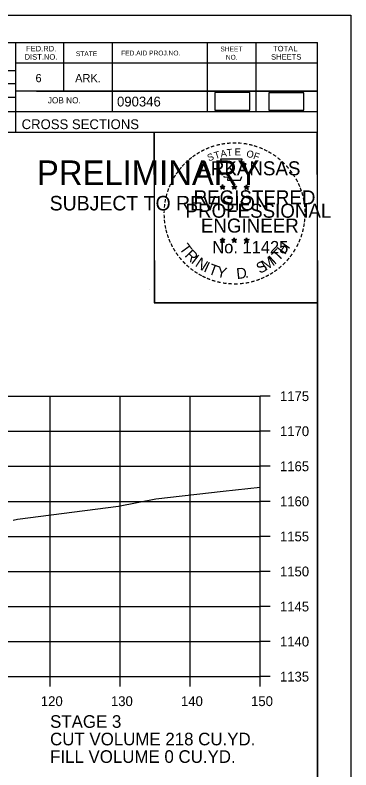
# Model space of a CAD drawing. Extents: x 1368971 to 1374497, y 378717 to 381839.
# Drawn here: x 1371167.7 to 1371215.6, y 379036.1 to 379143.8 of the extents above; entities that cross this region are included whole.
import ezdxf

# ---------------------------------------------------------------- set-up
doc = ezdxf.new("R2010")
doc.units = 0
for name, color, linetype in [('R_Axis', 7, 'Continuous'), ('R_Axis Annot', 7, 'Continuous'), ('R_Border', 7, 'Continuous'), ('R_Border PE', 7, 'Continuous'), ('R_Border Prem', 7, 'Continuous'), ('R_Exist Surface', 7, 'Continuous'), ('R_Grid', 7, 'Continuous'), ('R_No Plot', 7, 'Continuous'), ('R_Water', 7, 'Continuous')]:
    doc.layers.add(name, color=color, linetype=linetype)

msp = doc.modelspace()

# ---------------------------------------------------------------- linework, layer by layer
at = {"layer": 'R_Axis'}
for p, q in [((1371202.71, 379049.4), (1371202.71, 379089.4)), ((1371204.11, 379089.4), (1371202.71, 379089.4)), ((1371204.11, 379084.4), (1371202.71, 379084.4)), ((1371204.11, 379079.4), (1371202.71, 379079.4)), ((1371204.11, 379074.4), (1371202.71, 379074.4)), ((1371204.11, 379069.4), (1371202.71, 379069.4)), ((1371204.11, 379064.4), (1371202.71, 379064.4)), ((1371204.11, 379059.4), (1371202.71, 379059.4)), ((1371204.11, 379054.4), (1371202.71, 379054.4)), ((1370902.71, 379049.4), (1371202.71, 379049.4)), ((1371172.71, 379048), (1371172.71, 379049.4)), ((1371182.71, 379048), (1371182.71, 379049.4)), ((1371192.71, 379048), (1371192.71, 379049.4)), ((1371202.71, 379048), (1371202.71, 379049.4)), ((1371204.11, 379049.4), (1371202.71, 379049.4))]:
    msp.add_line(p, q, dxfattribs=at)
at = {"layer": 'R_Border'}
for p, q in [((1370894.71, 379139.86), (1371210.89, 379139.86)), ((1371167.79, 379139.86), (1371167.79, 379127.06)), ((1371174.63, 379139.86), (1371174.63, 379132.92)), ((1371181.57, 379139.86), (1371181.57, 379129.98)), ((1371195.15, 379139.86), (1371195.15, 379129.98)), ((1371202.09, 379139.86), (1371202.09, 379129.98)), ((1371210.89, 378934.4), (1371210.89, 379139.86)), ((1371210.89, 379136.92), (1371167.79, 379136.92)), ((1371210.89, 379136.94), (1371210.89, 379136.94)), ((1371128.63, 379135.84), (1371167.79, 379135.84)), ((1371128.63, 379133.98), (1371167.79, 379133.98)), ((1371210.89, 379132.92), (1371167.79, 379132.92)), ((1371170.75, 379132.92), (1371210.89, 379132.92)), ((1371128.63, 379132.04), (1371167.79, 379132.04)), ((1371210.89, 379129.98), (1371128.63, 379129.98)), ((1371167.79, 379127.06), (1371210.89, 379127.06))]:
    msp.add_line(p, q, dxfattribs=at)
at = {"layer": 'R_Border PE'}
for p, q in [((1371197.32, 379119.57), (1371197.28, 379119.32)), ((1371197.32, 379119.2), (1371197.32, 379119.57)), ((1371197.32, 379119.57), (1371197.37, 379119.32)), ((1371198.99, 379119.57), (1371198.95, 379119.32)), ((1371198.99, 379119.2), (1371198.99, 379119.57)), ((1371198.99, 379119.57), (1371199.04, 379119.32)), ((1371200.76, 379119.56), (1371200.72, 379119.3)), ((1371200.76, 379119.19), (1371200.76, 379119.56)), ((1371200.76, 379119.56), (1371200.81, 379119.31)), ((1371196.97, 379119.31), (1371197.32, 379119.2)), ((1371196.97, 379119.31), (1371197.23, 379119.27)), ((1371196.97, 379119.31), (1371197.21, 379119.19)), ((1371197.11, 379118.91), (1371197.32, 379119.2)), ((1371197.11, 379118.91), (1371197.23, 379119.15)), ((1371197.11, 379118.91), (1371197.32, 379119.12)), ((1371197.67, 379119.31), (1371197.32, 379119.2)), ((1371197.54, 379118.91), (1371197.32, 379119.2)), ((1371197.54, 379118.91), (1371197.32, 379119.12)), ((1371197.67, 379119.31), (1371197.38, 379119.27)), ((1371197.54, 379118.91), (1371197.4, 379119.2)), ((1371197.67, 379119.31), (1371197.47, 379119.21)), ((1371198.64, 379119.31), (1371198.99, 379119.2)), ((1371198.64, 379119.31), (1371198.9, 379119.27)), ((1371198.64, 379119.31), (1371198.88, 379119.19)), ((1371198.78, 379118.91), (1371198.99, 379119.2)), ((1371198.78, 379118.91), (1371198.9, 379119.15)), ((1371198.78, 379118.91), (1371198.99, 379119.12)), ((1371199.34, 379119.31), (1371198.99, 379119.2)), ((1371199.21, 379118.91), (1371198.99, 379119.2)), ((1371199.21, 379118.91), (1371198.99, 379119.12)), ((1371199.34, 379119.31), (1371199.05, 379119.27)), ((1371199.21, 379118.91), (1371199.07, 379119.2)), ((1371199.34, 379119.31), (1371199.14, 379119.21)), ((1371200.41, 379119.3), (1371200.76, 379119.19)), ((1371200.41, 379119.3), (1371200.66, 379119.26)), ((1371200.41, 379119.3), (1371200.64, 379119.18)), ((1371200.54, 379118.89), (1371200.76, 379119.19)), ((1371200.54, 379118.89), (1371200.67, 379119.14)), ((1371200.54, 379118.89), (1371200.75, 379119.11)), ((1371200.97, 379118.89), (1371200.75, 379119.11)), ((1371201.1, 379119.3), (1371200.76, 379119.19)), ((1371200.97, 379118.89), (1371200.76, 379119.19)), ((1371201.1, 379119.3), (1371200.82, 379119.25)), ((1371200.97, 379118.89), (1371200.83, 379119.19)), ((1371201.1, 379119.3), (1371200.9, 379119.2)), ((1371197.32, 379112), (1371197.28, 379111.74)), ((1371197.32, 379111.63), (1371197.32, 379112)), ((1371197.32, 379112), (1371197.37, 379111.75)), ((1371198.99, 379112), (1371198.95, 379111.74)), ((1371198.99, 379111.63), (1371198.99, 379112)), ((1371198.99, 379112), (1371199.04, 379111.75)), ((1371200.75, 379111.99), (1371200.71, 379111.73)), ((1371200.75, 379111.62), (1371200.75, 379111.99)), ((1371200.75, 379111.99), (1371200.8, 379111.74)), ((1371196.97, 379111.74), (1371197.32, 379111.63)), ((1371196.97, 379111.74), (1371197.22, 379111.7)), ((1371196.97, 379111.74), (1371197.21, 379111.62)), ((1371197.1, 379111.33), (1371197.32, 379111.63)), ((1371197.1, 379111.33), (1371197.23, 379111.58)), ((1371197.1, 379111.33), (1371197.32, 379111.55)), ((1371197.67, 379111.74), (1371197.32, 379111.63)), ((1371197.53, 379111.33), (1371197.32, 379111.63)), ((1371197.53, 379111.33), (1371197.32, 379111.55)), ((1371197.67, 379111.74), (1371197.38, 379111.69)), ((1371197.53, 379111.33), (1371197.39, 379111.62)), ((1371197.67, 379111.74), (1371197.46, 379111.64)), ((1371198.64, 379111.74), (1371198.99, 379111.63)), ((1371198.64, 379111.74), (1371198.89, 379111.7)), ((1371198.64, 379111.74), (1371198.88, 379111.62)), ((1371198.77, 379111.33), (1371198.99, 379111.63)), ((1371198.77, 379111.33), (1371198.9, 379111.58)), ((1371198.77, 379111.33), (1371198.99, 379111.55)), ((1371199.33, 379111.74), (1371198.99, 379111.63)), ((1371199.2, 379111.33), (1371198.99, 379111.63)), ((1371199.2, 379111.33), (1371198.99, 379111.55)), ((1371199.33, 379111.74), (1371199.05, 379111.69)), ((1371199.2, 379111.33), (1371199.06, 379111.62)), ((1371199.33, 379111.74), (1371199.13, 379111.64)), ((1371200.41, 379111.73), (1371200.75, 379111.62)), ((1371200.41, 379111.73), (1371200.66, 379111.69)), ((1371200.41, 379111.73), (1371200.64, 379111.61)), ((1371200.54, 379111.32), (1371200.75, 379111.62)), ((1371200.54, 379111.32), (1371200.66, 379111.57)), ((1371200.54, 379111.32), (1371200.75, 379111.54)), ((1371201.1, 379111.73), (1371200.75, 379111.62)), ((1371200.97, 379111.32), (1371200.75, 379111.62)), ((1371200.97, 379111.32), (1371200.75, 379111.54)), ((1371201.1, 379111.73), (1371200.82, 379111.68)), ((1371200.97, 379111.32), (1371200.83, 379111.61)), ((1371201.1, 379111.73), (1371200.9, 379111.63))]:
    msp.add_line(p, q, dxfattribs=at)
for points in [[(1371197.01, 379123.19), (1371197.28, 379122.37)], [(1371200.53, 379122.27), (1371200.67, 379122.55), (1371199.98, 379122.53), (1371200.13, 379123.19), (1371197.01, 379123.19)], [(1371197.51, 379120.77), (1371197.51, 379120.68), (1371198.07, 379120.66), (1371198.02, 379120.19), (1371199.89, 379120.19), (1371200.09, 379120.73)], [(1371197.32, 379119.57), (1371197.54, 379118.91), (1371196.97, 379119.31), (1371197.67, 379119.31), (1371197.11, 379118.91), (1371197.32, 379119.57)], [(1371198.99, 379119.57), (1371199.21, 379118.91), (1371198.64, 379119.31), (1371199.34, 379119.31), (1371198.78, 379118.91), (1371198.99, 379119.57)], [(1371200.76, 379119.56), (1371200.97, 379118.89), (1371200.41, 379119.3), (1371201.1, 379119.3), (1371200.54, 379118.89), (1371200.76, 379119.56)], [(1371197.32, 379112), (1371197.53, 379111.33), (1371196.97, 379111.74), (1371197.67, 379111.74), (1371197.1, 379111.33), (1371197.32, 379112)], [(1371198.99, 379112), (1371199.2, 379111.33), (1371198.64, 379111.74), (1371199.33, 379111.74), (1371198.77, 379111.33), (1371198.99, 379112)], [(1371200.75, 379111.99), (1371200.97, 379111.32), (1371200.41, 379111.73), (1371201.1, 379111.73), (1371200.54, 379111.32), (1371200.75, 379111.99)]]:
    msp.add_lwpolyline(points, dxfattribs=at)
for centre, radius in [((1371197.32, 379119.2), 0.172), ((1371197.32, 379119.2), 0.145), ((1371197.32, 379119.2), 0.116), ((1371197.32, 379119.2), 0.0991), ((1371197.32, 379119.2), 0.0747), ((1371197.32, 379119.2), 0.0495), ((1371197.32, 379119.2), 0.0296), ((1371198.99, 379119.2), 0.172), ((1371198.99, 379119.2), 0.145), ((1371198.99, 379119.2), 0.116), ((1371198.99, 379119.2), 0.0991), ((1371198.99, 379119.2), 0.0747), ((1371198.99, 379119.2), 0.0495), ((1371198.99, 379119.2), 0.0296), ((1371200.76, 379119.19), 0.172), ((1371200.76, 379119.19), 0.145), ((1371200.76, 379119.19), 0.116), ((1371200.76, 379119.19), 0.0991), ((1371200.76, 379119.19), 0.0747), ((1371200.76, 379119.19), 0.0495), ((1371200.76, 379119.19), 0.0296), ((1371197.32, 379111.63), 0.172), ((1371197.32, 379111.63), 0.145), ((1371197.32, 379111.63), 0.116), ((1371197.32, 379111.63), 0.0991), ((1371197.32, 379111.63), 0.0747), ((1371197.32, 379111.63), 0.0495), ((1371197.32, 379111.63), 0.0296), ((1371198.99, 379111.63), 0.172), ((1371198.99, 379111.63), 0.145), ((1371198.99, 379111.63), 0.116), ((1371198.99, 379111.63), 0.0991), ((1371198.99, 379111.63), 0.0747), ((1371198.99, 379111.63), 0.0495), ((1371198.99, 379111.63), 0.0296), ((1371200.75, 379111.62), 0.172), ((1371200.75, 379111.62), 0.145), ((1371200.75, 379111.62), 0.116), ((1371200.75, 379111.62), 0.0991), ((1371200.75, 379111.62), 0.0747), ((1371200.75, 379111.62), 0.0495), ((1371200.75, 379111.62), 0.0296)]:
    msp.add_circle(centre, radius, dxfattribs=at)
at = {"layer": 'R_Exist Surface'}
msp.add_lwpolyline([(1371167.45, 379071.74), (1371168.08, 379071.84), (1371182.48, 379073.69), (1371187.78, 379074.74), (1371197.4, 379075.86), (1371202.71, 379076.43)], dxfattribs=at)
at = {"layer": 'R_Grid'}
for p, q in [((1370902.71, 379089.4), (1371202.71, 379089.4)), ((1371172.71, 379049.4), (1371172.71, 379089.4)), ((1371182.71, 379049.4), (1371182.71, 379089.4)), ((1371192.71, 379049.4), (1371192.71, 379089.4)), ((1371202.71, 379049.4), (1371202.71, 379089.4)), ((1370902.71, 379084.4), (1371202.71, 379084.4)), ((1370902.71, 379079.4), (1371202.71, 379079.4)), ((1370902.71, 379074.4), (1371202.71, 379074.4)), ((1370902.71, 379069.4), (1371202.71, 379069.4)), ((1370902.71, 379064.4), (1371202.71, 379064.4)), ((1370902.71, 379059.4), (1371202.71, 379059.4)), ((1370902.71, 379054.4), (1371202.71, 379054.4)), ((1370902.71, 379049.4), (1371202.71, 379049.4))]:
    msp.add_line(p, q, dxfattribs=at)
at = {"layer": 'R_No Plot'}
for p, q in [((1370882.31, 379143.75), (1371215.64, 379143.75)), ((1371186.92, 379104.6), (1371186.92, 379104.6))]:
    msp.add_line(p, q, dxfattribs=at)
for points in [[(1370882.3, 379143.75), (1371215.64, 379143.75), (1371215.64, 378930.42), (1370882.3, 378930.42)], [(1371128.63, 379139.86), (1371128.63, 379129.98), (1371164.36, 379129.98), (1371164.36, 379127.06), (1371187.56, 379127.06), (1371187.56, 379102.73), (1371210.89, 379102.73), (1371210.89, 378934.4), (1370894.71, 378934.4), (1370894.71, 379139.86)], [(1371187.56, 379127.06), (1371210.77, 379127.06), (1371210.89, 379102.73), (1371187.68, 379102.73)]]:
    msp.add_lwpolyline(points, close=True, dxfattribs=at)
at = {"layer": 'R_Water'}
for points in [[(1371196.21, 379130.21), (1371201.21, 379130.21), (1371201.21, 379132.71), (1371196.21, 379132.71)], [(1371203.94, 379130.18), (1371208.94, 379130.18), (1371208.94, 379132.68), (1371203.94, 379132.68)]]:
    msp.add_lwpolyline(points, close=True, dxfattribs=at)

# ---------------------------------------------------------------- texts
at = {"layer": 'R_Axis Annot'}
for s, height, p in [('1175', 1.4, (1371205.51, 379088.7)), ('1170', 1.4, (1371205.51, 379083.7)), ('1165', 1.4, (1371205.51, 379078.7)), ('1160', 1.4, (1371205.51, 379073.7)), ('1155', 1.4, (1371205.51, 379068.7)), ('1150', 1.4, (1371205.51, 379063.7)), ('1145', 1.4, (1371205.51, 379058.7)), ('1140', 1.4, (1371205.51, 379053.7)), ('1135', 1.4, (1371205.51, 379048.7)), ('120', 1.4, (1371171.39, 379045.2)), ('130', 1.4, (1371181.39, 379045.2)), ('140', 1.4, (1371191.39, 379045.2)), ('150', 1.4, (1371201.39, 379045.2)), ('STAGE 3', 1.8, (1371172.71, 379042.1)), ('CUT VOLUME 218 CU.YD.', 1.8, (1371172.71, 379039.6)), ('FILL VOLUME 0 CU.YD.', 1.8, (1371172.71, 379037.1))]:
    msp.add_text(s, height=height, dxfattribs=at).set_placement(p)
at = {"layer": 'R_Border'}
for s, height, p in [('FED.RD.', 0.782, (1371169.27, 379138.58)), ('SHEET', 0.684, (1371197.01, 379138.58)), ('TOTAL', 0.782, (1371204.53, 379138.58)), ('DIST.NO.', 0.782, (1371169.07, 379137.4)), ('STATE', 0.684, (1371176.39, 379137.9)), ('FED.AID PROJ.NO.', 0.684, (1371182.85, 379138)), ('NO.', 0.684, (1371197.79, 379137.4)), ('SHEETS', 0.782, (1371204.25, 379137.4)), ('6', 1.17, (1371170.63, 379134.18)), ('ARK.', 1.172, (1371176.29, 379134.18)), ('JOB NO.', 0.879, (1371172.39, 379131.16)), ('CROSS SECTIONS', 1.4, (1371168.65, 379127.49))]:
    msp.add_text(s, height=height, dxfattribs=at).set_placement(p)
msp.add_text('090346', height=1.4, rotation=360, dxfattribs=at).set_placement((1371182.26, 379130.72))
at = {"layer": 'R_Border PE'}
for s, height, rotation, p in [('-', 1.6, 24.3072, (1371195.13, 379124.05)), ('-', 1.6, 19.1761, (1371195.76, 379124.32)), ('-', 1.6, 13.6301, (1371196.51, 379124.56)), ('-', 1.6, 10.2193, (1371197.19, 379124.72)), ('-', 1.6, 5.8968, (1371197.92, 379124.83)), ('-', 1.6, 0.1862, (1371198.69, 379124.9)), ('-', 1.6, 357.743, (1371199.41, 379124.89)), ('-', 1.6, 352.1617, (1371200.16, 379124.84)), ('-', 1.6, 347.2049, (1371200.88, 379124.72)), ('-', 1.6, 342.3362, (1371201.51, 379124.57)), ('-', 1.6, 337.8551, (1371202.25, 379124.34)), ('-', 1.6, 36.2317, (1371193.32, 379122.97)), ('-', 1.6, 34.0636, (1371193.9, 379123.36)), ('-', 1.6, 28.7918, (1371194.49, 379123.73)), ('S', 1, 21.594, (1371195.37, 379122.87)), ('T', 1, 16.4036, (1371196.28, 379123.2)), ('A', 1, 11.2132, (1371197.11, 379123.45)), ('T', 1, 6.0228, (1371197.96, 379123.62)), ('E', 1, 0.8323, (1371199.06, 379123.73)), ('O', 1, 350.4515, (1371200.67, 379123.52)), ('F', 1, 340.0707, (1371201.62, 379123.29)), ('-', 1.6, 334.1211, (1371202.88, 379124.07)), ('-', 1.6, 329.6409, (1371203.46, 379123.79)), ('-', 1.6, 325.8627, (1371204.1, 379123.43)), ('-', 1.6, 42.9622, (1371192.41, 379122.17)), ('-', 1.6, 38.9507, (1371192.84, 379122.59)), ('-', 1.6, 320.5297, (1371204.71, 379123)), ('-', 1.6, 315.5786, (1371205.31, 379122.51)), ('-', 1.6, 50.6142, (1371191.56, 379121.21)), ('-', 1.6, 48.423, (1371191.96, 379121.7)), ('-', 1.6, 309.8797, (1371205.88, 379121.96)), ('-', 1.6, 306.6522, (1371206.4, 379121.36)), ('-', 1.6, 58.0706, (1371190.82, 379120.12)), ('-', 1.6, 54.2325, (1371191.15, 379120.64)), ('-', 1.4, 303.6753, (1371206.89, 379120.79)), ('-', 1.6, 67.7743, (1371190.25, 379118.89)), ('-', 1.6, 62.8713, (1371190.51, 379119.5)), ('-', 1.6, 299.6684, (1371207.21, 379120.19)), ('-', 1.6, 294.6628, (1371207.53, 379119.58)), ('-', 1.6, 72.3945, (1371190.03, 379118.26)), ('-', 1.6, 290.5728, (1371207.79, 379119)), ('-', 1.6, 285.1233, (1371208.02, 379118.42)), ('-', 1.6, 81.2013, (1371189.7, 379116.83)), ('-', 1.6, 75.461, (1371189.83, 379117.55)), ('-', 1.6, 280.5493, (1371208.22, 379117.68)), ('-', 1.6, 85.1863, (1371189.63, 379116.14)), ('-', 1.6, 276.5962, (1371208.38, 379116.91)), ('-', 1.6, 94.1959, (1371189.64, 379114.72)), ('-', 1.6, 89.0622, (1371189.6, 379115.44)), ('-', 1.6, 274.3301, (1371208.44, 379116.19)), ('-', 1.6, 269.9407, (1371208.48, 379115.55)), ('-', 1.6, 98.9479, (1371189.71, 379114.05)), ('-', 1.6, 263.5172, (1371208.46, 379114.89)), ('-', 1.6, 101.7149, (1371189.84, 379113.32)), ('-', 1.6, 105.4578, (1371190, 379112.72)), ('-', 1.6, 255.7626, (1371208.28, 379113.56)), ('-', 1.6, 260.9953, (1371208.39, 379114.23)), ('-', 1.6, 109.0874, (1371190.22, 379112.09)), ('-', 1.6, 252.8681, (1371208.1, 379112.84)), ('-', 1.6, 114.0643, (1371190.47, 379111.49)), ('-', 1.6, 115.7288, (1371190.78, 379110.88)), ('T', 1.54, 306.0406, (1371191.08, 379110.47)), ('H', 1.54, 54.6088, (1371206.2, 379109.5)), ('-', 1.6, 244.6197, (1371207.61, 379111.53)), ('-', 1.6, 247.8887, (1371207.87, 379112.16)), ('-', 1.6, 120.4471, (1371191.14, 379110.29)), ('-', 1.6, 125.8934, (1371191.54, 379109.73)), ('R', 1.54, 314.005, (1371191.84, 379109.42)), ('T', 1.54, 46.6444, (1371205.31, 379108.56)), ('-', 1.6, 239.0712, (1371207.22, 379110.78)), ('-', 1.6, 130.7181, (1371192, 379109.18)), ('I', 1.54, 321.9694, (1371192.74, 379108.49)), ('N', 1.54, 326.5002, (1371193.31, 379108.02)), ('M', 1.54, 32.6563, (1371203.46, 379107.24)), ('I', 1.54, 42.1136, (1371204.75, 379108.08)), ('-', 1.6, 231.2538, (1371206.39, 379109.56)), ('-', 1.6, 233.8452, (1371206.82, 379110.13)), ('-', 1.6, 134.2238, (1371192.52, 379108.63)), ('-', 1.6, 138.9338, (1371193.04, 379108.17)), ('-', 1.6, 144.6463, (1371193.6, 379107.76)), ('I', 1.54, 335.3603, (1371194.52, 379107.23)), ('T', 1.54, 339.8912, (1371195.18, 379106.9)), ('Y', 1.54, 347.8556, (1371196.39, 379106.46)), ('D', 1.54, 6.3969, (1371199.38, 379106.1)), ('S', 1.54, 26.9312, (1371202.62, 379106.83)), ('-', 1.6, 221.0851, (1371205.39, 379108.49)), ('-', 1.6, 225.7653, (1371205.91, 379109)), ('-', 1.6, 148.0898, (1371194.16, 379107.39)), ('-', 1.6, 151.5704, (1371194.74, 379107.07)), ('-', 1.6, 154.6002, (1371195.26, 379106.82)), ('-', 1.6, 207.3568, (1371203.74, 379107.29)), ('-', 1.6, 212.2491, (1371204.3, 379107.63)), ('-', 1.6, 215.7363, (1371204.84, 379108.02)), ('-', 1.6, 158.5612, (1371195.88, 379106.57)), ('-', 1.6, 162.7983, (1371196.57, 379106.35)), ('-', 1.6, 167.5555, (1371197.29, 379106.19)), ('-', 1.6, 173.1155, (1371198.06, 379106.08)), ('-', 1.6, 176.5183, (1371198.81, 379106.03)), ('-', 1.6, 185.8167, (1371200.36, 379106.12)), ('-', 1.6, 191.2858, (1371201.1, 379106.25)), ('.', 1.54, 13.7642, (1371200.57, 379106.23)), ('-', 1.6, 195.4743, (1371201.82, 379106.45)), ('-', 1.6, 200.7184, (1371202.5, 379106.69)), ('-', 1.6, 204.2516, (1371203.12, 379106.97)), ('-', 1.6, 181.5918, (1371199.55, 379106.04))]:
    msp.add_text(s, height=height, rotation=rotation, dxfattribs=at).set_placement(p)
for s, height, p in [('ARKANSAS', 2, (1371193.87, 379120.9)), ('REGISTERED', 2, (1371193.19, 379116.76)), ('DWB', 0.01, (1371197.31, 379119.2)), ('DWB', 0.01, (1371198.98, 379119.2)), ('DWB', 0.01, (1371200.74, 379119.19)), ('PROFESSIONAL', 2, (1371192.04, 379114.85)), ('ENGINEER', 2, (1371194.23, 379112.73)), ('No. 11425', 1.757, (1371195.86, 379109.78)), ('DWB', 0.01, (1371197.31, 379111.63)), ('DWB', 0.01, (1371198.97, 379111.63)), ('DWB', 0.01, (1371200.74, 379111.62))]:
    msp.add_text(s, height=height, dxfattribs=at).set_placement(p)
at = {"layer": 'R_Border Prem'}
for s, height, p in [('PRELIMINARY', 3.5, (1371170.84, 379119.52)), ('DWB', 0.01, (1371171.59, 379121.37)), ('SUBJECT TO REVISION', 2.0751, (1371172.65, 379115.89))]:
    msp.add_text(s, height=height, dxfattribs=at).set_placement(p)

doc.saveas('drawing.dxf')
